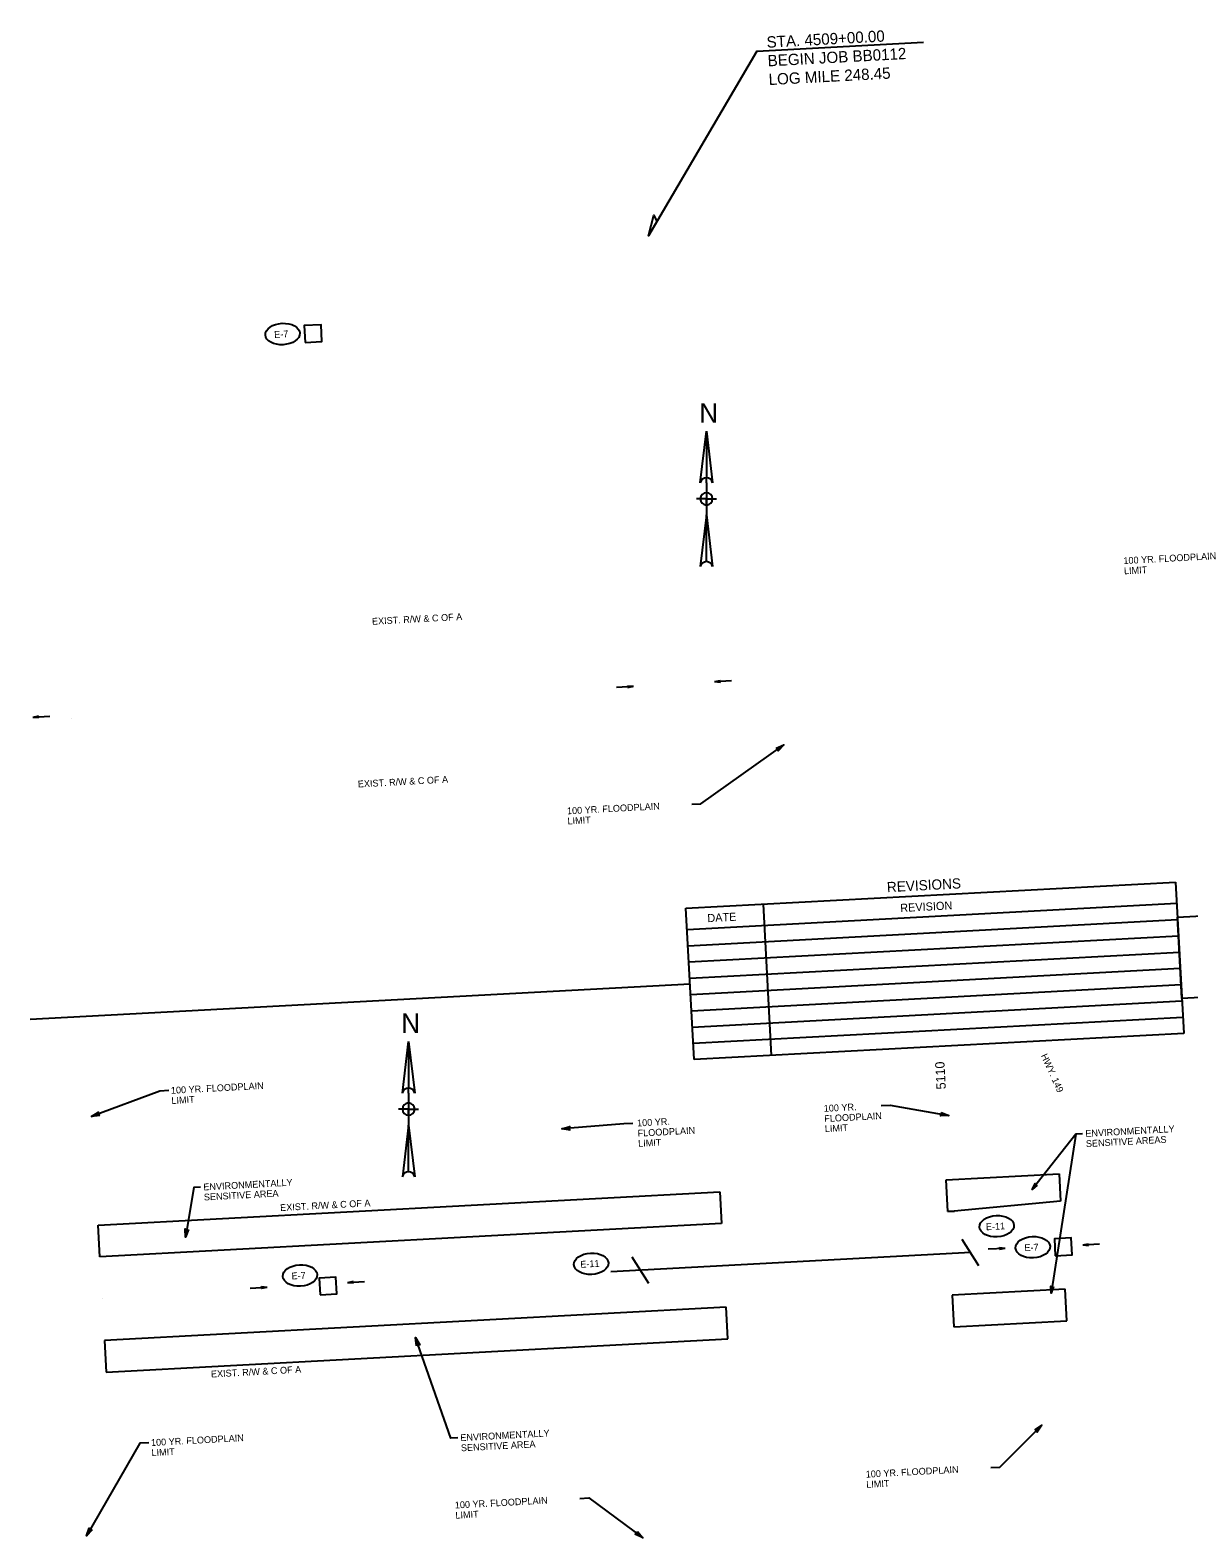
# Model space of a CAD drawing. Extents: x 251072 to 254282, y 223355 to 226019.
# Drawn here: x 251072 to 253119, y 223355 to 226019 of the extents above; entities that cross this region are included whole.
import ezdxf

# ---------------------------------------------------------------- set-up
doc = ezdxf.new("R2010")
doc.units = 0
for name, color, linetype in [('24X36', 7, 'Continuous'), ('DRAINAGE', 7, 'Continuous'), ('Level 1', 7, 'Continuous'), ('Level 24', 7, 'Continuous'), ('Level 30', 7, 'Continuous'), ('Level 42', 7, 'Continuous'), ('Level 58', 7, 'Continuous'), ('Level 59', 7, 'Continuous'), ('R_Water Annot', 7, 'Continuous'), ('STATIONING1', 7, 'Continuous')]:
    doc.layers.add(name, color=color, linetype=linetype)

msp = doc.modelspace()

# ---------------------------------------------------------------- linework, layer by layer
at = {"layer": '24X36'}
for p, q in [((252717.6, 223882.5), (252747, 223836)), ((252134.6, 223851.4), (252163.9, 223804.9))]:
    msp.add_line(p, q, dxfattribs=at)
for points in [[(251557.4, 225467.5), (251587.3, 225469.1), (251585.7, 225498.9), (251555.8, 225497.3)], [(252882.8, 223853.4), (252912.6, 223855), (252911, 223884.8), (252881.2, 223883.2)], [(251583.9, 223784.2), (251613.7, 223785.8), (251612.1, 223815.6), (251582.3, 223814)]]:
    msp.add_lwpolyline(points, close=True, dxfattribs=at)
at = {"layer": 'DRAINAGE'}
for p, q in [((252127.7, 224860.8), (252137.7, 224859.8)), ((252127.8, 224857.8), (252127.7, 224860.8)), ((252127.7, 224860.5), (252136.1, 224859.7)), ((252127.7, 224860.3), (252134.3, 224859.6)), ((252127.7, 224860), (252132.7, 224859.6)), ((252127.7, 224859.8), (252131, 224859.5)), ((252127.7, 224859.5), (252129.3, 224859.4)), ((252127.7, 224859.1), (252129.3, 224859.4)), ((252127.8, 224857.8), (252137.7, 224859.8)), ((252127.8, 224858), (252136.1, 224859.7)), ((252127.8, 224858.3), (252134.3, 224859.6)), ((252127.8, 224858.6), (252132.7, 224859.6)), ((252127.8, 224858.8), (252131, 224859.5)), ((252290.6, 224869.5), (252280.7, 224867.5)), ((252290.8, 224866.5), (252280.7, 224867.5)), ((252290.6, 224869.3), (252282.4, 224867.6)), ((252290.8, 224866.8), (252282.4, 224867.6)), ((252290.6, 224869), (252284.1, 224867.7)), ((252290.7, 224867.1), (252284.1, 224867.7)), ((252290.6, 224868.8), (252285.7, 224867.8)), ((252290.7, 224867.3), (252285.7, 224867.8)), ((252290.7, 224868.5), (252287.4, 224867.9)), ((252290.7, 224867.6), (252287.4, 224867.9)), ((252290.7, 224868.3), (252289.1, 224868)), ((252290.7, 224867.8), (252289.1, 224868)), ((252290.8, 224866.5), (252290.6, 224869.5)), ((251086.3, 224806.8), (251076.4, 224804.7)), ((251086.4, 224803.8), (251076.4, 224804.7)), ((251086.3, 224806.5), (251078, 224804.8)), ((251086.4, 224804), (251078, 224804.8)), ((251086.3, 224806.3), (251079.8, 224804.9)), ((251086.4, 224804.3), (251079.8, 224804.9)), ((251086.3, 224806), (251081.4, 224805)), ((251086.4, 224804.5), (251081.4, 224805)), ((251086.3, 224805.8), (251083.1, 224805.1)), ((251086.4, 224804.8), (251083.1, 224805.1)), ((251086.3, 224805.5), (251084.8, 224805.2)), ((251086.4, 224805), (251084.8, 224805.2)), ((251086.4, 224803.8), (251086.3, 224806.8)), ((252784.4, 223868), (252794.4, 223867)), ((252784.5, 223865), (252784.4, 223868)), ((252784.4, 223867.8), (252792.8, 223867)), ((252784.4, 223867.5), (252791.1, 223866.9)), ((252784.4, 223867.3), (252789.4, 223866.8)), ((252784.4, 223867), (252787.7, 223866.7)), ((252784.4, 223866.8), (252786, 223866.6)), ((252784.5, 223865), (252794.4, 223867)), ((252784.5, 223865.3), (252792.8, 223867)), ((252784.5, 223865.5), (252791.1, 223866.9)), ((252784.5, 223865.8), (252789.4, 223866.8)), ((252784.5, 223866), (252787.7, 223866.7)), ((252784.5, 223866.3), (252786, 223866.6)), ((252941.2, 223874), (252931.3, 223871.9)), ((252941.3, 223871), (252931.3, 223871.9)), ((252941.2, 223873.8), (252932.9, 223872)), ((252941.3, 223871.3), (252932.9, 223872)), ((252941.2, 223873.5), (252934.7, 223872.1)), ((252941.3, 223871.5), (252934.7, 223872.1)), ((252941.2, 223873.3), (252936.3, 223872.2)), ((252941.3, 223871.8), (252936.3, 223872.2)), ((252941.2, 223873), (252938, 223872.3)), ((252941.3, 223872), (252938, 223872.3)), ((252941.2, 223872.7), (252939.7, 223872.4)), ((252941.3, 223872.3), (252939.7, 223872.4)), ((252941.3, 223871), (252941.2, 223874)), ((251642.4, 223807.6), (251632.5, 223805.5)), ((251642.6, 223804.6), (251632.5, 223805.5)), ((251642.5, 223807.3), (251634.2, 223805.6)), ((251642.6, 223804.8), (251634.2, 223805.6)), ((251642.5, 223807), (251635.9, 223805.7)), ((251642.6, 223805.1), (251635.9, 223805.7)), ((251642.5, 223806.8), (251637.6, 223805.8)), ((251642.6, 223805.3), (251637.6, 223805.8)), ((251642.5, 223806.5), (251639.3, 223805.9)), ((251642.6, 223805.6), (251639.3, 223805.9)), ((251642.5, 223806.3), (251640.9, 223806)), ((251642.5, 223805.8), (251640.9, 223806)), ((251642.6, 223804.6), (251642.4, 223807.6)), ((251480.2, 223798.8), (251490.3, 223797.9)), ((251480.4, 223795.8), (251480.2, 223798.8)), ((251480.2, 223798.6), (251488.6, 223797.8)), ((251480.2, 223798.3), (251486.9, 223797.7)), ((251480.2, 223798.1), (251485.2, 223797.6)), ((251480.3, 223797.8), (251483.5, 223797.5)), ((251480.3, 223796.1), (251488.6, 223797.8)), ((251480.3, 223796.3), (251486.9, 223797.7)), ((251480.3, 223796.6), (251485.2, 223797.6)), ((251480.3, 223797.6), (251481.9, 223797.4)), ((251480.3, 223796.9), (251483.5, 223797.5)), ((251480.3, 223797.1), (251481.9, 223797.4)), ((251480.4, 223795.8), (251490.3, 223797.9))]:
    msp.add_line(p, q, dxfattribs=at)
at = {"layer": 'Level 1'}
for p, q in [((252255.7, 225219.4), (252266.6, 225310.9)), ((252266.6, 225310.9), (252277.5, 225219.4)), ((252266.6, 225310.9), (252266.6, 225228.1)), ((252266.6, 225219.4), (252266.6, 225228.1)), ((252266.6, 225219.4), (252266.6, 225202)), ((252255.3, 225191.1), (252249.2, 225191.1)), ((252266.6, 225191.1), (252256.1, 225191.1)), ((252266.6, 225202), (252266.6, 225191.1)), ((252266.6, 225191.1), (252266.6, 225180.2)), ((252266.6, 225191.1), (252277.5, 225191.1)), ((252266.6, 225180.2), (252266.6, 225191.1)), ((252277.5, 225191.1), (252284.1, 225191.1)), ((252277.5, 225191.1), (252277.5, 225191.1)), ((252266.6, 225180.2), (252266.6, 225162.8)), ((252266.6, 225162.8), (252255.7, 225071.4)), ((252266.6, 225080.1), (252266.6, 225162.8)), ((252266.6, 225162.8), (252277.5, 225071.4)), ((251144, 224803.2), (251144, 224803.2)), ((252230.4, 224467.5), (253095.4, 224513.8)), ((253095.4, 224513.8), (253109.7, 224246.4)), ((252232.4, 224430.1), (253097.4, 224476.4)), ((252366.8, 224474.8), (252381.1, 224207.3)), ((252244.7, 224200), (252230.4, 224467.5)), ((252233.9, 224401.3), (253098.9, 224447.7)), ((252235.5, 224372.6), (253100.5, 224418.9)), ((252237, 224343.8), (253102, 224390.1)), ((252238.6, 224315), (253103.6, 224361.4)), ((251071.8, 224271.3), (252237.6, 224333.8)), ((252240.1, 224286.3), (253105.1, 224332.6)), ((252241.6, 224257.5), (253106.6, 224303.9)), ((252243.2, 224228.8), (253108.2, 224275.1)), ((251729.3, 224140.8), (251740.2, 224232.2)), ((251740.2, 224232.2), (251751.1, 224140.8)), ((251740.2, 224232.2), (251740.2, 224149.5)), ((253109.7, 224246.4), (252244.7, 224200)), ((253109.7, 224246.4), (253109.7, 224246.4)), ((251740.2, 224140.8), (251740.2, 224149.5)), ((251740.2, 224140.8), (251740.2, 224123.3)), ((251728.9, 224112.4), (251722.8, 224112.4)), ((251740.2, 224112.4), (251729.6, 224112.4)), ((251740.2, 224123.3), (251740.2, 224112.4)), ((251740.2, 224112.4), (251740.2, 224101.6)), ((251740.2, 224112.4), (251751.1, 224112.4)), ((251740.2, 224101.6), (251740.2, 224112.4)), ((251740.2, 224101.6), (251740.2, 224084.1)), ((251751.1, 224112.4), (251757.6, 224112.4)), ((251751.1, 224112.4), (251751.1, 224112.4)), ((251740.2, 224084.1), (251729.3, 223992.7)), ((251740.2, 224001.4), (251740.2, 224084.1)), ((251740.2, 224084.1), (251751.1, 223992.7)), ((252097.7, 223825.5), (252733.4, 223859.6)), ((251199, 223777.4), (251199, 223777.4))]:
    msp.add_line(p, q, dxfattribs=at)
msp.add_lwpolyline([(253098.7, 224452), (253522.9, 224474.7), (253530.6, 224330.9), (253106.4, 224308.2)], close=True, dxfattribs=at)
for centre, radius, start, end in [((252266.6, 225217), 11.2, 90, 167.3196), ((252266.6, 225217), 11.2, 12.6804, 90), ((252266.6, 225191.1), 10.9, 90, 180), ((252266.6, 225191.1), 10.9, 180, 270), ((252266.6, 225191.1), 10.9, 0, 90), ((252266.6, 225191.1), 10.9, 270, 0), ((252266.6, 225068.9), 11.2, 90, 167.3196), ((252266.6, 225068.9), 11.2, 12.6804, 90), ((251740.2, 224138.3), 11.2, 90, 167.3196), ((251740.2, 224138.3), 11.2, 12.6804, 90), ((251740.2, 224112.5), 10.9, 90, 180), ((251740.2, 224112.5), 10.9, 180, 270), ((251740.2, 224112.5), 10.9, 0, 90), ((251740.2, 224112.5), 10.9, 270, 0), ((251740.2, 223990.3), 11.2, 90, 167.3196), ((251740.2, 223990.3), 11.2, 12.6804, 90)]:
    msp.add_arc(centre, radius, start, end, dxfattribs=at)
at = {"layer": 'Level 24'}
for points in [[(252355.8, 225982.5), (252649.9, 225998.3)], [(252355.8, 225982.5), (252164.2, 225655.7)], [(252241, 224651.4), (252256.9, 224652.2), (252403.4, 224756.5)], [(251316.8, 224145.3), (251300.8, 224144.4), (251180.3, 224099.2)], [(252575.5, 224118.7), (252591.4, 224119.5), (252694.8, 224101.1)], [(252136.7, 224087.1), (252120.7, 224086.2), (252011, 224077.4)], [(252919, 224068.4), (252841.7, 223970.3)], [(252931.2, 224069.1), (252919, 224068.4), (252875.6, 223787.3)], [(251373, 223974.6), (251360.8, 223973.9), (251346.4, 223886.3)], [(251827.1, 223531.4), (251814.9, 223530.7), (251752.7, 223708.6)], [(252768.8, 223478.9), (252784.7, 223479.8), (252858.9, 223553.9)], [(251281.6, 223522.9), (251265.6, 223522), (251171.6, 223358.1)], [(252042.9, 223424.4), (252058.9, 223425.2), (252154.2, 223354.8)]]:
    msp.add_lwpolyline(points, dxfattribs=at)
at = {"layer": 'Level 30'}
for centre in [(251517.8, 225482.4), (252779.4, 223905.5), (252843.1, 223868.4), (252062.9, 223839.2), (251548.5, 223818.4)]:
    msp.add_ellipse(centre, major_axis=(30.4, 1.6), ratio=0.622507, dxfattribs=at)
at = {"layer": 'Level 42'}
for p, q in [((252692.9, 223931.5), (252704.9, 223932.2)), ((252704.1, 223932.1), (252692.9, 223931.5)), ((252293.4, 223910.1), (251195, 223851.3)), ((252900.5, 223794.5), (252700.8, 223783.8)), ((252301.3, 223762.4), (251202.9, 223703.5)), ((252304.3, 223706.4), (252301.3, 223762.4)), ((252703.8, 223727.8), (252903.5, 223738.5)), ((251205.9, 223647.6), (252304.3, 223706.4))]:
    msp.add_line(p, q, dxfattribs=at)
for points in [[(252689.9, 223987.5), (252889.6, 223998.2)], [(252889.6, 223998.2), (252892.2, 223949.8)], [(251192, 223907.2), (252290.4, 223966.1)], [(252290.4, 223966.1), (252293.4, 223910.1)], [(252692.9, 223931.5), (252689.9, 223987.5)], [(252892.2, 223949.8), (252704.1, 223932.1)], [(251195, 223851.3), (251192, 223907.2)], [(252700.8, 223783.8), (252703.8, 223727.8)], [(252903.5, 223738.5), (252900.5, 223794.5)], [(251202.9, 223703.5), (251205.9, 223647.6)]]:
    msp.add_lwpolyline(points, dxfattribs=at)
at = {"layer": 'Level 58'}
for points in [[(252389.9, 224750.6), (252403.4, 224756.5), (252393.4, 224745.7), (252393.6, 224749.5)], [(251194.8, 224101.4), (251180.3, 224099.2), (251192.7, 224107), (251191.5, 224103.4)], [(252681.1, 224106.6), (252694.8, 224101.1), (252680.1, 224100.7), (252683, 224103.2)], [(252025.6, 224075.5), (252011, 224077.4), (252025.1, 224081.5), (252022.9, 224078.3)], [(252851, 223978.1), (252841.7, 223970.3), (252847.1, 223981.2), (252847.8, 223978.1)], [(251351.7, 223900), (251346.4, 223886.3), (251345.8, 223901), (251348.4, 223898.1)], [(252879.9, 223798.8), (252875.6, 223787.3), (252875, 223799.5), (252877.1, 223797.2)], [(251754.6, 223694), (251752.7, 223708.6), (251760.3, 223696), (251756.7, 223697.3)], [(252846.6, 223545.9), (252858.9, 223553.9), (252850.8, 223541.6), (252850.4, 223545.4)], [(251181.4, 223369.1), (251171.6, 223358.1), (251176.1, 223372), (251177.6, 223368.5)], [(252144.6, 223365.9), (252154.2, 223354.8), (252140.9, 223361.1), (252144.7, 223362)]]:
    msp.add_lwpolyline(points, close=True, dxfattribs=at)
at = {"layer": 'Level 59'}
msp.add_lwpolyline([(252179.1, 225681.1), (252164.2, 225655.7), (252173.4, 225692.4)], close=True, dxfattribs=at)
at = {"layer": 'STATIONING1'}
for p, q in [((252107.8, 224858.3), (252137.7, 224859.8)), ((252127.7, 224860.8), (252137.7, 224859.8)), ((252127.8, 224857.8), (252127.7, 224860.8)), ((252127.7, 224860.5), (252136.1, 224859.7)), ((252127.7, 224860.3), (252134.3, 224859.6)), ((252127.7, 224860), (252132.7, 224859.6)), ((252127.7, 224859.8), (252131, 224859.5)), ((252127.7, 224859.5), (252129.3, 224859.4)), ((252127.7, 224859.1), (252129.3, 224859.4)), ((252127.8, 224857.8), (252137.7, 224859.8)), ((252127.8, 224858), (252136.1, 224859.7)), ((252127.8, 224858.3), (252134.3, 224859.6)), ((252127.8, 224858.6), (252132.7, 224859.6)), ((252127.8, 224858.8), (252131, 224859.5)), ((252290.6, 224869.5), (252280.7, 224867.5)), ((252310.6, 224869.2), (252280.7, 224867.5)), ((252290.8, 224866.5), (252280.7, 224867.5)), ((252290.6, 224869.3), (252282.4, 224867.6)), ((252290.8, 224866.8), (252282.4, 224867.6)), ((252290.6, 224869), (252284.1, 224867.7)), ((252290.7, 224867.1), (252284.1, 224867.7)), ((252290.6, 224868.8), (252285.7, 224867.8)), ((252290.7, 224867.3), (252285.7, 224867.8)), ((252290.7, 224868.5), (252287.4, 224867.9)), ((252290.7, 224867.6), (252287.4, 224867.9)), ((252290.7, 224868.3), (252289.1, 224868)), ((252290.7, 224867.8), (252289.1, 224868)), ((252290.8, 224866.5), (252290.6, 224869.5)), ((251086.3, 224806.8), (251076.4, 224804.7)), ((251106.3, 224806.4), (251076.4, 224804.7)), ((251086.4, 224803.8), (251076.4, 224804.7)), ((251086.3, 224806.5), (251078, 224804.8)), ((251086.4, 224804), (251078, 224804.8)), ((251086.3, 224806.3), (251079.8, 224804.9)), ((251086.4, 224804.3), (251079.8, 224804.9)), ((251086.3, 224806), (251081.4, 224805)), ((251086.4, 224804.5), (251081.4, 224805)), ((251086.3, 224805.8), (251083.1, 224805.1)), ((251086.4, 224804.8), (251083.1, 224805.1)), ((251086.3, 224805.5), (251084.8, 224805.2)), ((251086.4, 224805), (251084.8, 224805.2)), ((251086.4, 224803.8), (251086.3, 224806.8)), ((252764.5, 223865.5), (252794.4, 223867)), ((252784.4, 223868), (252794.4, 223867)), ((252784.5, 223865), (252784.4, 223868)), ((252784.4, 223867.8), (252792.8, 223867)), ((252784.4, 223867.5), (252791.1, 223866.9)), ((252784.4, 223867.3), (252789.4, 223866.8)), ((252784.4, 223867), (252787.7, 223866.7)), ((252784.4, 223866.8), (252786, 223866.6)), ((252784.5, 223865), (252794.4, 223867)), ((252784.5, 223865.3), (252792.8, 223867)), ((252784.5, 223865.5), (252791.1, 223866.9)), ((252784.5, 223865.8), (252789.4, 223866.8)), ((252784.5, 223866), (252787.7, 223866.7)), ((252784.5, 223866.3), (252786, 223866.6)), ((252941.2, 223874), (252931.3, 223871.9)), ((252961.2, 223873.6), (252931.3, 223871.9)), ((252941.3, 223871), (252931.3, 223871.9)), ((252941.2, 223873.8), (252932.9, 223872)), ((252941.3, 223871.3), (252932.9, 223872)), ((252941.2, 223873.5), (252934.7, 223872.1)), ((252941.3, 223871.5), (252934.7, 223872.1)), ((252941.2, 223873.3), (252936.3, 223872.2)), ((252941.3, 223871.8), (252936.3, 223872.2)), ((252941.2, 223873), (252938, 223872.3)), ((252941.3, 223872), (252938, 223872.3)), ((252941.2, 223872.7), (252939.7, 223872.4)), ((252941.3, 223872.3), (252939.7, 223872.4)), ((252941.3, 223871), (252941.2, 223874)), ((251642.4, 223807.6), (251632.5, 223805.5)), ((251662.5, 223807.2), (251632.5, 223805.5)), ((251642.6, 223804.6), (251632.5, 223805.5)), ((251642.5, 223807.3), (251634.2, 223805.6)), ((251642.6, 223804.8), (251634.2, 223805.6)), ((251642.5, 223807), (251635.9, 223805.7)), ((251642.6, 223805.1), (251635.9, 223805.7)), ((251642.5, 223806.8), (251637.6, 223805.8)), ((251642.6, 223805.3), (251637.6, 223805.8)), ((251642.5, 223806.5), (251639.3, 223805.9)), ((251642.6, 223805.6), (251639.3, 223805.9)), ((251642.5, 223806.3), (251640.9, 223806)), ((251642.5, 223805.8), (251640.9, 223806)), ((251642.6, 223804.6), (251642.4, 223807.6)), ((251460.3, 223796.3), (251490.3, 223797.9)), ((251480.2, 223798.8), (251490.3, 223797.9)), ((251480.4, 223795.8), (251480.2, 223798.8)), ((251480.2, 223798.6), (251488.6, 223797.8)), ((251480.2, 223798.3), (251486.9, 223797.7)), ((251480.2, 223798.1), (251485.2, 223797.6)), ((251480.3, 223797.8), (251483.5, 223797.5)), ((251480.3, 223796.1), (251488.6, 223797.8)), ((251480.3, 223796.3), (251486.9, 223797.7)), ((251480.3, 223796.6), (251485.2, 223797.6)), ((251480.3, 223797.6), (251481.9, 223797.4)), ((251480.3, 223796.9), (251483.5, 223797.5)), ((251480.3, 223797.1), (251481.9, 223797.4)), ((251480.4, 223795.8), (251490.3, 223797.9))]:
    msp.add_line(p, q, dxfattribs=at)

# ---------------------------------------------------------------- texts
at = {"layer": 'Level 1'}
for p in [(252254, 225325.9), (251727.5, 224247.3)]:
    msp.add_text('N', height=34.2, dxfattribs=at).set_placement(p)
for s, p in [('REVISION', (252609.3, 224460.7)), ('DATE', (252268.5, 224442.8))]:
    msp.add_text(s, height=14.4, rotation=3.0666, dxfattribs=at).set_placement(p)
at = {"layer": 'Level 24'}
for s, height, rotation, p in [('STA. 4509+00.00', 20, 3.0667, (252373.4, 225988.2)), ('BEGIN JOB BB0112', 20, 3.0667, (252375.2, 225955.3)), ('LOG MILE 248.45', 20, 3.0667, (252377, 225922.3)), ('100 YR. FLOODPLAIN', 12, 3.0666, (253003.5, 225075.7)), ('LIMIT', 12, 3.0666, (253004.5, 225057.7)), ('EXIST. R/W & C OF A', 12, 3.0666, (251676, 224968.5)), ('EXIST. R/W & C OF A', 12, 3.0666, (251651, 224681)), ('100 YR. FLOODPLAIN', 12, 3.0666, (252020.5, 224633.5)), ('LIMIT', 12, 3.0666, (252021.4, 224615.6)), ('HWY. 149', 12, 294.3986, (252857, 224207.1)), ('100 YR. FLOODPLAIN', 12, 3.0666, (251320.8, 224139.5)), ('LIMIT', 12, 3.0666, (251321.7, 224121.5)), ('100 YR.', 12, 3.0666, (252474.1, 224107.6)), ('FLOODPLAIN', 12, 3.0666, (252475.1, 224089.6)), ('100 YR.', 12, 3.0666, (252144.3, 224081.8)), ('FLOODPLAIN', 12, 3.0666, (252145.3, 224063.8)), ('LIMIT', 12, 3.0666, (252476, 224071.7)), ('ENVIRONMENTALLY', 12, 3.0666, (252936.3, 224063.4)), ('LIMIT', 12, 3.0666, (252146.2, 224045.8)), ('SENSITIVE AREAS', 12, 3.0666, (252937.2, 224045.4)), ('ENVIRONMENTALLY', 12, 3.0666, (251378.1, 223968.8)), ('SENSITIVE AREA', 12, 3.0666, (251379, 223950.9)), ('EXIST. R/W & C OF A', 12, 3.0666, (251513.8, 223932.3)), ('EXIST. R/W & C OF A', 12, 3.0666, (251391.5, 223638.2)), ('ENVIRONMENTALLY', 12, 3.0666, (251832.1, 223525.7)), ('100 YR. FLOODPLAIN', 12, 3.0666, (251285.6, 223517)), ('LIMIT', 12, 3.0666, (251286.5, 223499.1)), ('SENSITIVE AREA', 12, 3.0666, (251833.1, 223507.7)), ('100 YR. FLOODPLAIN', 12, 3.0666, (252548.3, 223461.1)), ('LIMIT', 12, 3.0666, (252549.2, 223443.1)), ('100 YR. FLOODPLAIN', 12, 3.0666, (251822.4, 223406.6)), ('LIMIT', 12, 3.0666, (251823.4, 223388.6))]:
    msp.add_text(s, height=height, rotation=rotation, dxfattribs=at).set_placement(p)
at = {"layer": 'Level 30'}
for s, height, p in [('E-7', 12, (251503.2, 225475.5)), ('REVISIONS', 18, (252585.8, 224495.8)), ('E-11', 12, (252760.6, 223898.3)), ('E-7', 12, (252828.6, 223861.4)), ('E-11', 12, (252044.1, 223832.1)), ('E-7', 12, (251533.9, 223811.5))]:
    msp.add_text(s, height=height, rotation=3.0666, dxfattribs=at).set_placement(p)
at = {"layer": 'R_Water Annot'}
msp.add_text('5110', height=16.5, rotation=93.0667, dxfattribs=at).set_placement((252689.5, 224147.9))

doc.saveas('drawing.dxf')
